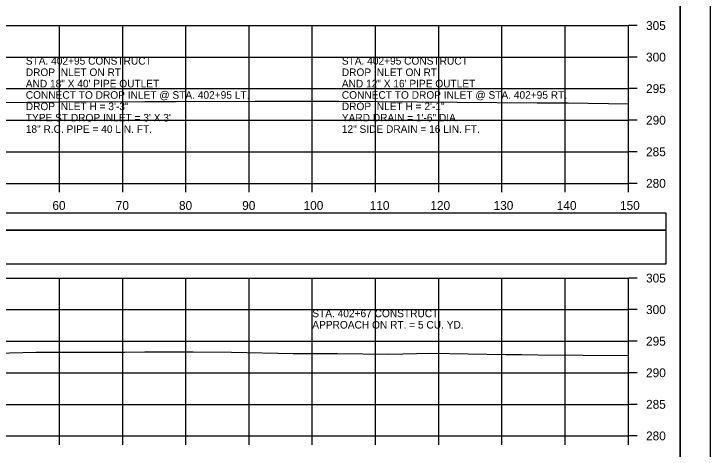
# Model space of a CAD drawing. Extents: x 1370538 to 1372872, y 376220 to 381127.
# Drawn here: x 1370761.4 to 1370871.5, y 376535.7 to 376604.6 of the extents above; entities that cross this region are included whole.
import ezdxf

# ---------------------------------------------------------------- set-up
doc = ezdxf.new("R2010")
doc.units = 0
for name, color, linetype in [('R_Border Notes', 7, 'Continuous'), ('R_Border PE', 7, 'Continuous'), ('R_Border Prem', 7, 'Continuous'), ('R_Dimension', 7, 'Continuous'), ('R_Grid', 7, 'Continuous'), ('R_No Plot', 7, 'Continuous'), ('R_Water Annot', 7, 'Continuous'), ('T_Detection Zones', 7, 'Continuous')]:
    doc.layers.add(name, color=color, linetype=linetype)

msp = doc.modelspace()

# ---------------------------------------------------------------- linework, layer by layer
at = {"layer": 'R_Border Notes'}
msp.add_line((1370866.79, 376437.75), (1370866.79, 376643.21), dxfattribs=at)
at = {"layer": 'R_Border Prem'}
for p, q in [((1370858.61, 376577.75), (1370858.61, 376602.75)), ((1370860.01, 376602.75), (1370858.61, 376602.75)), ((1370860.01, 376597.75), (1370858.61, 376597.75)), ((1370860.01, 376592.75), (1370858.61, 376592.75)), ((1370860.01, 376587.75), (1370858.61, 376587.75)), ((1370860.01, 376582.75), (1370858.61, 376582.75)), ((1370558.61, 376577.75), (1370858.61, 376577.75)), ((1370768.61, 376576.35), (1370768.61, 376577.75)), ((1370778.61, 376576.35), (1370778.61, 376577.75)), ((1370788.61, 376576.35), (1370788.61, 376577.75)), ((1370798.61, 376576.35), (1370798.61, 376577.75)), ((1370808.61, 376576.35), (1370808.61, 376577.75)), ((1370818.61, 376576.35), (1370818.61, 376577.75)), ((1370828.61, 376576.35), (1370828.61, 376577.75)), ((1370838.61, 376576.35), (1370838.61, 376577.75)), ((1370848.61, 376576.35), (1370848.61, 376577.75)), ((1370858.61, 376576.35), (1370858.61, 376577.75)), ((1370860.01, 376577.75), (1370858.61, 376577.75)), ((1370858.61, 376537.75), (1370858.61, 376562.75)), ((1370860.01, 376562.75), (1370858.61, 376562.75)), ((1370860.01, 376557.75), (1370858.61, 376557.75)), ((1370860.01, 376552.75), (1370858.61, 376552.75)), ((1370860.01, 376547.75), (1370858.61, 376547.75)), ((1370860.01, 376542.75), (1370858.61, 376542.75)), ((1370558.61, 376537.75), (1370858.61, 376537.75)), ((1370768.61, 376536.35), (1370768.61, 376537.75)), ((1370778.61, 376536.35), (1370778.61, 376537.75)), ((1370788.61, 376536.35), (1370788.61, 376537.75)), ((1370798.61, 376536.35), (1370798.61, 376537.75)), ((1370808.61, 376536.35), (1370808.61, 376537.75)), ((1370818.61, 376536.35), (1370818.61, 376537.75)), ((1370828.61, 376536.35), (1370828.61, 376537.75)), ((1370838.61, 376536.35), (1370838.61, 376537.75)), ((1370848.61, 376536.35), (1370848.61, 376537.75)), ((1370858.61, 376536.35), (1370858.61, 376537.75)), ((1370860.01, 376537.75), (1370858.61, 376537.75))]:
    msp.add_line(p, q, dxfattribs=at)
at = {"layer": 'R_Dimension'}
for points in [[(1370758.37, 376590.57), (1370768.52, 376590.65), (1370782.14, 376590.71), (1370785.34, 376590.72), (1370786.32, 376590.73), (1370787.07, 376590.73), (1370799.56, 376590.76), (1370812.82, 376590.79), (1370818.87, 376590.69), (1370844.21, 376590.5), (1370849.11, 376590.48), (1370858.61, 376590.32)], [(1370756.45, 376550.8), (1370764.92, 376551), (1370770.5, 376551.04), (1370778.95, 376551.02), (1370782.1, 376551.06), (1370789.77, 376551.05), (1370795.82, 376551.04), (1370805.57, 376550.82), (1370812.52, 376550.81), (1370820.7, 376550.71), (1370827.33, 376550.86), (1370839.23, 376550.67), (1370841.72, 376550.63), (1370844.28, 376550.59), (1370858.61, 376550.47)]]:
    msp.add_lwpolyline(points, dxfattribs=at)
at = {"layer": 'R_Grid'}
for p, q in [((1370558.61, 376602.75), (1370858.61, 376602.75)), ((1370768.61, 376577.75), (1370768.61, 376602.75)), ((1370778.61, 376577.75), (1370778.61, 376602.75)), ((1370788.61, 376577.75), (1370788.61, 376602.75)), ((1370798.61, 376577.75), (1370798.61, 376602.75)), ((1370808.61, 376577.75), (1370808.61, 376602.75)), ((1370818.61, 376577.75), (1370818.61, 376602.75)), ((1370828.61, 376577.75), (1370828.61, 376602.75)), ((1370838.61, 376577.75), (1370838.61, 376602.75)), ((1370848.61, 376577.75), (1370848.61, 376602.75)), ((1370858.61, 376577.75), (1370858.61, 376602.75)), ((1370558.61, 376597.75), (1370858.61, 376597.75)), ((1370558.61, 376592.75), (1370858.61, 376592.75)), ((1370558.61, 376587.75), (1370858.61, 376587.75)), ((1370558.61, 376582.75), (1370858.61, 376582.75)), ((1370558.61, 376577.75), (1370858.61, 376577.75)), ((1370558.61, 376562.75), (1370858.61, 376562.75)), ((1370768.61, 376537.75), (1370768.61, 376562.75)), ((1370778.61, 376537.75), (1370778.61, 376562.75)), ((1370788.61, 376537.75), (1370788.61, 376562.75)), ((1370798.61, 376537.75), (1370798.61, 376562.75)), ((1370808.61, 376537.75), (1370808.61, 376562.75)), ((1370818.61, 376537.75), (1370818.61, 376562.75)), ((1370828.61, 376537.75), (1370828.61, 376562.75)), ((1370838.61, 376537.75), (1370838.61, 376562.75)), ((1370848.61, 376537.75), (1370848.61, 376562.75)), ((1370858.61, 376537.75), (1370858.61, 376562.75)), ((1370558.61, 376557.75), (1370858.61, 376557.75)), ((1370558.61, 376552.75), (1370858.61, 376552.75)), ((1370558.61, 376547.75), (1370858.61, 376547.75)), ((1370558.61, 376542.75), (1370858.61, 376542.75)), ((1370558.61, 376537.75), (1370858.61, 376537.75))]:
    msp.add_line(p, q, dxfattribs=at)
at = {"layer": 'R_No Plot'}
for points in [[(1370538.2, 376647.11), (1370871.54, 376647.11), (1370871.54, 376433.77), (1370538.2, 376433.77)], [(1370784.53, 376643.21), (1370784.53, 376633.33), (1370820.26, 376633.33), (1370820.26, 376630.41), (1370843.46, 376630.41), (1370843.46, 376606.08), (1370866.79, 376606.08), (1370866.79, 376437.75), (1370550.61, 376437.75), (1370550.61, 376643.21)]]:
    msp.add_lwpolyline(points, close=True, dxfattribs=at)
at = {"layer": 'T_Detection Zones'}
for points in [[(1370552.62, 376570.31), (1370864.59, 376570.31), (1370864.59, 376573.01), (1370552.62, 376573.01)], [(1370552.62, 376564.98), (1370864.59, 376564.98), (1370864.59, 376570.31), (1370552.62, 376570.31)]]:
    msp.add_lwpolyline(points, close=True, dxfattribs=at)

# ---------------------------------------------------------------- texts
at = {"layer": 'R_Border PE'}
for s, p in [('305', (1370861.41, 376602.05)), ('300', (1370861.41, 376597.05)), ('295', (1370861.41, 376592.05)), ('290', (1370861.41, 376587.05)), ('285', (1370861.41, 376582.05)), ('280', (1370861.41, 376577.05)), ('60', (1370767.49, 376573.55)), ('70', (1370777.52, 376573.55)), ('80', (1370787.52, 376573.55)), ('90', (1370797.52, 376573.55)), ('100', (1370807.23, 376573.55)), ('110', (1370817.69, 376573.55)), ('120', (1370827.29, 376573.55)), ('130', (1370837.29, 376573.55)), ('140', (1370847.29, 376573.55)), ('150', (1370857.29, 376573.55)), ('305', (1370861.41, 376562.05)), ('300', (1370861.41, 376557.05)), ('295', (1370861.41, 376552.05)), ('290', (1370861.41, 376547.05)), ('285', (1370861.41, 376542.05)), ('280', (1370861.41, 376537.05))]:
    msp.add_text(s, height=1.4, dxfattribs=at).set_placement(p)
at = {"layer": 'R_Water Annot'}
for s, p in [('STA. 402+95 CONSTRUCT', (1370763.28, 376596.55)), ('STA. 402+95 CONSTRUCT', (1370813.28, 376596.55)), ('DROP INLET ON RT.', (1370763.28, 376594.75)), ('DROP INLET ON RT.', (1370813.28, 376594.75)), ('AND 18" X 40\' PIPE OUTLET', (1370763.28, 376592.95)), ('AND 12" X 16\' PIPE OUTLET', (1370813.28, 376592.95)), ('CONNECT TO DROP INLET @ STA. 402+95 LT.', (1370763.28, 376591.15)), ('CONNECT TO DROP INLET @ STA. 402+95 RT.', (1370813.28, 376591.15)), ('DROP INLET H = 3\'-3"', (1370763.28, 376589.35)), ('DROP INLET H = 2\'-1"', (1370813.28, 376589.35)), ("TYPE ST DROP INLET = 3' X 3'", (1370763.28, 376587.55)), ('YARD DRAIN = 1\'-6" DIA.', (1370813.28, 376587.55)), ('18" R.C. PIPE = 40 LIN. FT.', (1370763.28, 376585.75)), ('12" SIDE DRAIN = 16 LIN. FT.', (1370813.28, 376585.75)), ('STA. 402+67 CONSTRUCT', (1370808.61, 376556.55)), ('APPROACH ON RT. = 5 CU. YD.', (1370808.61, 376554.75))]:
    msp.add_text(s, height=1.2, dxfattribs=at).set_placement(p)

doc.saveas('drawing.dxf')
